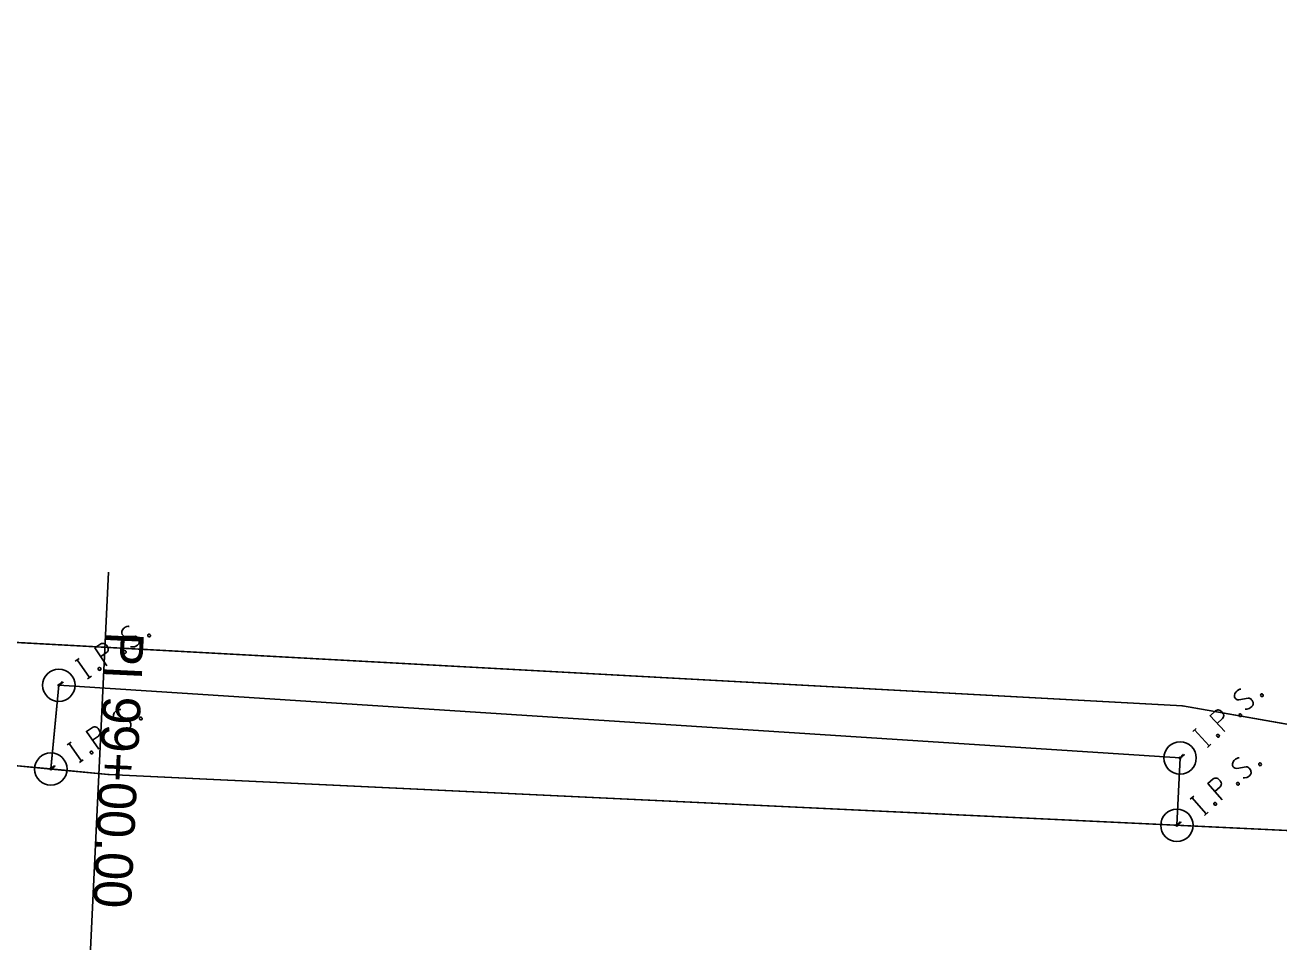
# Model space of a CAD drawing. Extents: x 2318731 to 2320621, y 732958 to 734198.
# Drawn here: x 2319231.8 to 2319324.8, y 733560.7 to 733628.7 of the extents above; entities that cross this region are included whole.
import ezdxf

# ---------------------------------------------------------------- set-up
doc = ezdxf.new("R2010")
doc.units = 0
for name, color, linetype in [('RW_P_Easement_Area', 7, 'Continuous'), ('RW_P_Esmt_SW', 7, 'Continuous'), ('RW_P_Esmt_TMP', 7, 'Continuous'), ('RW_P_Taking_Area', 7, 'Continuous'), ('RW_X_CL_100_Cardinal_Points', 7, 'Continuous'), ('RW_X_CL_500_Cardinal_Points', 7, 'Continuous'), ('SC_Scratch2', 7, 'Continuous'), ('SC_Scratch3', 7, 'Continuous'), ('SC_Scratch4', 7, 'Continuous'), ('SV_P_Control_Cells_Set', 7, 'Continuous'), ('SV_P_Mon_Cells_Set', 7, 'Continuous'), ('V-SURV-PARL-LINE', 7, 'Continuous')]:
    doc.layers.add(name, color=color, linetype=linetype)

msp = doc.modelspace()

# ---------------------------------------------------------------- linework, layer by layer
at = {"layer": 'RW_P_Easement_Area'}
for p, q in [((2319228.625, 733583.014), (2319317.642, 733578.163)), ((2319234.336, 733579.7), (2319233.745, 733573.486)), ((2319317.458, 733574.308), (2319234.336, 733579.7)), ((2319317.642, 733578.163), (2319387.147, 733565.99)), ((2319233.745, 733573.486), (2319227.772, 733574.054)), ((2319317.22, 733569.314), (2319317.458, 733574.308)), ((2319387.147, 733565.99), (2319317.22, 733569.314))]:
    msp.add_line(p, q, dxfattribs=at)
at = {"layer": 'RW_P_Esmt_SW'}
for p, q in [((2319233.745, 733573.486), (2319234.336, 733579.7)), ((2319233.745, 733573.486), (2319234.336, 733579.7)), ((2319234.336, 733579.7), (2319317.458, 733574.308)), ((2319234.336, 733579.7), (2319317.458, 733574.308)), ((2319317.458, 733574.308), (2319317.22, 733569.314)), ((2319317.458, 733574.308), (2319317.22, 733569.314))]:
    msp.add_line(p, q, dxfattribs=at)
at = {"layer": 'RW_P_Esmt_TMP'}
for p, q in [((2319228.625, 733583.016), (2319317.642, 733578.163)), ((2319317.642, 733578.163), (2319387.148, 733565.99))]:
    msp.add_line(p, q, dxfattribs=at)
at = {"layer": 'RW_P_Taking_Area'}
for p, q in [((2319233.745, 733573.486), (2319234.336, 733579.7)), ((2319234.336, 733579.7), (2319317.458, 733574.308)), ((2319317.458, 733574.308), (2319317.22, 733569.314)), ((2319238.014, 733573.079), (2319233.745, 733573.486)), ((2319317.22, 733569.314), (2319238.014, 733573.079))]:
    msp.add_line(p, q, dxfattribs=at)
at = {"layer": 'RW_X_CL_100_Cardinal_Points'}
msp.add_line((2319235.879, 733543.147), (2319238.016, 733588.096), dxfattribs=at)
at = {"layer": 'RW_X_CL_500_Cardinal_Points'}
msp.add_line((2319235.879, 733543.147), (2319238.016, 733588.096), dxfattribs=at)
at = {"layer": 'SC_Scratch2'}
msp.add_lwpolyline([(2319234.336, 733579.7), (2319317.451, 733574.309), (2319317.213, 733569.314), (2319238.014, 733573.079), (2319233.745, 733573.491)], close=True, dxfattribs=at)
at = {"layer": 'SC_Scratch3'}
msp.add_lwpolyline([(2319228.625, 733583.016), (2319227.772, 733574.054), (2319233.745, 733573.491), (2319234.336, 733579.7), (2319317.451, 733574.309), (2319317.213, 733569.314), (2319387.148, 733565.99), (2319317.634, 733578.164)], close=True, dxfattribs=at)
at = {"layer": 'SC_Scratch4'}
msp.add_lwpolyline([(2319238.014, 733573.079), (2319387.148, 733565.99), (2319438.367, 733857.203), (2319458.709, 733857.406), (2319402.048, 733535.248), (2319235.879, 733543.147), (2319201.733, 733546.397), (2319204.577, 733576.262)], close=True, dxfattribs=at)
at = {"layer": 'SV_P_Control_Cells_Set'}
for p, q in [((2319317.64, 733578.116), (2319317.645, 733578.21)), ((2319317.595, 733578.165), (2319317.69, 733578.161)), ((2319237.967, 733573.084), (2319238.061, 733573.075)), ((2319238.01, 733573.032), (2319238.018, 733573.126))]:
    msp.add_line(p, q, dxfattribs=at)
at = {"layer": 'SV_P_Mon_Cells_Set'}
for points in [[(2319239.559, 733584.062), (2319239.527, 733584.071), (2319239.485, 733584.073), (2319239.382, 733584.049), (2319239.267, 733584.002), (2319239.194, 733583.952), (2319239.167, 733583.934), (2319239.069, 733583.822), (2319239.011, 733583.692), (2319239.004, 733583.565), (2319239.042, 733583.469), (2319239.084, 733583.406), (2319239.159, 733583.335), (2319239.282, 733583.312), (2319239.996, 733583.338), (2319240.069, 733583.327), (2319240.116, 733583.298), (2319240.176, 733583.248), (2319240.219, 733583.185), (2319240.252, 733583.116), (2319240.271, 733583.068), (2319240.288, 733583.004), (2319240.298, 733582.95), (2319240.301, 733582.906), (2319240.295, 733582.856), (2319240.281, 733582.817), (2319240.259, 733582.771), (2319240.239, 733582.742), (2319240.164, 733582.676), (2319240.036, 733582.59), (2319239.939, 733582.555), (2319239.771, 733582.548), (2319239.656, 733582.561)], [(2319240.948, 733583.465), (2319240.993, 733583.496), (2319241.035, 733583.493), (2319241.09, 733583.47), (2319241.126, 733583.418), (2319241.127, 733583.358), (2319241.113, 733583.318), (2319241.068, 733583.287), (2319241.026, 733583.29), (2319240.971, 733583.313), (2319240.935, 733583.365), (2319240.934, 733583.426), (2319240.948, 733583.465)], [(2319237.899, 733581.145), (2319237.003, 733582.471), (2319237.441, 733582.767), (2319237.494, 733582.787), (2319237.572, 733582.81), (2319237.613, 733582.807), (2319237.655, 733582.805), (2319237.727, 733582.778), (2319237.789, 733582.744), (2319237.864, 733582.673), (2319237.949, 733582.547), (2319237.968, 733582.5), (2319237.992, 733582.425), (2319238.005, 733582.327), (2319237.989, 733582.271), (2319237.976, 733582.231), (2319237.945, 733582.18), (2319237.879, 733582.12), (2319237.44, 733581.824)], [(2319239.14, 733582.243), (2319239.185, 733582.273), (2319239.227, 733582.271), (2319239.282, 733582.248), (2319239.318, 733582.196), (2319239.319, 733582.135), (2319239.305, 733582.096), (2319239.26, 733582.065), (2319239.218, 733582.067), (2319239.162, 733582.091), (2319239.127, 733582.143), (2319239.126, 733582.203), (2319239.14, 733582.243)], [(2319235.56, 733581.495), (2319235.852, 733581.693)], [(2319236.602, 733580.268), (2319235.706, 733581.594)], [(2319237.277, 733580.983), (2319237.322, 733581.014), (2319237.364, 733581.012), (2319237.419, 733580.988), (2319237.455, 733580.936), (2319237.456, 733580.876), (2319237.442, 733580.836), (2319237.397, 733580.806), (2319237.355, 733580.808), (2319237.3, 733580.831), (2319237.264, 733580.883), (2319237.263, 733580.944), (2319237.277, 733580.983)], [(2319236.456, 733580.17), (2319236.748, 733580.367)], [(2319234.389, 733579.795), (2319234.402, 733579.807)], [(2319234.446, 733579.739), (2319234.395, 733579.801)], [(2319234.44, 733579.734), (2319234.453, 733579.745)], [(2319234.507, 733579.789), (2319234.456, 733579.851), (2319234.476, 733579.868), (2319234.479, 733579.869), (2319234.482, 733579.871), (2319234.485, 733579.871), (2319234.487, 733579.871), (2319234.49, 733579.87), (2319234.494, 733579.868), (2319234.498, 733579.865), (2319234.502, 733579.859), (2319234.504, 733579.857), (2319234.505, 733579.853), (2319234.506, 733579.849), (2319234.506, 733579.846), (2319234.505, 733579.844), (2319234.504, 733579.841), (2319234.501, 733579.838), (2319234.481, 733579.821)], [(2319234.477, 733579.778), (2319234.479, 733579.78), (2319234.481, 733579.78), (2319234.484, 733579.779), (2319234.486, 733579.777), (2319234.486, 733579.774), (2319234.485, 733579.772), (2319234.483, 733579.77), (2319234.481, 733579.77), (2319234.478, 733579.771), (2319234.476, 733579.773), (2319234.476, 733579.776), (2319234.477, 733579.778)], [(2319234.575, 733579.942), (2319234.574, 733579.943), (2319234.572, 733579.943), (2319234.567, 733579.941), (2319234.561, 733579.938), (2319234.558, 733579.935), (2319234.556, 733579.934), (2319234.552, 733579.928), (2319234.55, 733579.921), (2319234.55, 733579.915), (2319234.552, 733579.91), (2319234.555, 733579.907), (2319234.559, 733579.904), (2319234.565, 733579.904), (2319234.601, 733579.908), (2319234.604, 733579.908), (2319234.607, 733579.907), (2319234.61, 733579.905), (2319234.612, 733579.902), (2319234.614, 733579.899), (2319234.616, 733579.896), (2319234.617, 733579.893), (2319234.617, 733579.891), (2319234.618, 733579.888), (2319234.618, 733579.886), (2319234.617, 733579.884), (2319234.616, 733579.881), (2319234.615, 733579.88), (2319234.612, 733579.876), (2319234.606, 733579.871), (2319234.601, 733579.869), (2319234.593, 733579.868), (2319234.587, 733579.868)], [(2319234.563, 733579.85), (2319234.565, 733579.852), (2319234.567, 733579.852), (2319234.57, 733579.851), (2319234.572, 733579.848), (2319234.573, 733579.845), (2319234.572, 733579.843), (2319234.57, 733579.842), (2319234.568, 733579.841), (2319234.565, 733579.842), (2319234.563, 733579.845), (2319234.563, 733579.848), (2319234.563, 733579.85)], [(2319234.647, 733579.919), (2319234.649, 733579.921), (2319234.652, 733579.921), (2319234.654, 733579.92), (2319234.656, 733579.918), (2319234.657, 733579.915), (2319234.656, 733579.913), (2319234.654, 733579.911), (2319234.652, 733579.911), (2319234.649, 733579.912), (2319234.647, 733579.914), (2319234.647, 733579.917), (2319234.647, 733579.919)], [(2319321.971, 733579.401), (2319321.938, 733579.404), (2319321.896, 733579.401), (2319321.798, 733579.361), (2319321.691, 733579.298), (2319321.627, 733579.238), (2319321.602, 733579.215), (2319321.522, 733579.09), (2319321.485, 733578.953), (2319321.496, 733578.826), (2319321.548, 733578.737), (2319321.599, 733578.682), (2319321.684, 733578.622), (2319321.808, 733578.617), (2319322.51, 733578.75), (2319322.585, 733578.751), (2319322.635, 733578.728), (2319322.703, 733578.688), (2319322.754, 733578.632), (2319322.797, 733578.569), (2319322.823, 733578.525), (2319322.85, 733578.463), (2319322.868, 733578.411), (2319322.877, 733578.369), (2319322.878, 733578.318), (2319322.871, 733578.277), (2319322.856, 733578.229), (2319322.84, 733578.197), (2319322.775, 733578.121), (2319322.662, 733578.016), (2319322.572, 733577.968), (2319322.407, 733577.935), (2319322.291, 733577.931)], [(2319323.433, 733579.018), (2319323.473, 733579.055), (2319323.515, 733579.059), (2319323.573, 733579.044), (2319323.616, 733578.998), (2319323.626, 733578.939), (2319323.619, 733578.898), (2319323.578, 733578.86), (2319323.537, 733578.856), (2319323.478, 733578.871), (2319323.436, 733578.917), (2319323.426, 733578.977), (2319323.433, 733579.018)], [(2319238.931, 733577.891), (2319238.898, 733577.899), (2319238.857, 733577.901), (2319238.754, 733577.876), (2319238.639, 733577.828), (2319238.567, 733577.778), (2319238.54, 733577.76), (2319238.443, 733577.647), (2319238.386, 733577.516), (2319238.38, 733577.389), (2319238.419, 733577.294), (2319238.461, 733577.231), (2319238.537, 733577.161), (2319238.659, 733577.138), (2319239.373, 733577.171), (2319239.447, 733577.161), (2319239.494, 733577.132), (2319239.555, 733577.082), (2319239.598, 733577.02), (2319239.631, 733576.951), (2319239.651, 733576.903), (2319239.668, 733576.839), (2319239.679, 733576.785), (2319239.682, 733576.741), (2319239.676, 733576.691), (2319239.663, 733576.652), (2319239.641, 733576.606), (2319239.621, 733576.577), (2319239.547, 733576.51), (2319239.42, 733576.423), (2319239.324, 733576.387), (2319239.155, 733576.379), (2319239.04, 733576.391)], [(2319240.324, 733577.306), (2319240.369, 733577.337), (2319240.411, 733577.335), (2319240.467, 733577.312), (2319240.503, 733577.26), (2319240.504, 733577.2), (2319240.491, 733577.16), (2319240.446, 733577.129), (2319240.404, 733577.131), (2319240.348, 733577.154), (2319240.313, 733577.206), (2319240.311, 733577.266), (2319240.324, 733577.306)], [(2319320.765, 733576.269), (2319319.681, 733577.445), (2319320.07, 733577.804), (2319320.119, 733577.832), (2319320.193, 733577.866), (2319320.234, 733577.869), (2319320.276, 733577.873), (2319320.351, 733577.857), (2319320.418, 733577.833), (2319320.502, 733577.774), (2319320.605, 733577.663), (2319320.631, 733577.618), (2319320.666, 733577.547), (2319320.693, 733577.453), (2319320.686, 733577.395), (2319320.679, 733577.354), (2319320.656, 733577.298), (2319320.599, 733577.229), (2319320.21, 733576.871)], [(2319321.828, 733577.539), (2319321.868, 733577.576), (2319321.91, 733577.58), (2319321.968, 733577.566), (2319322.011, 733577.519), (2319322.021, 733577.46), (2319322.013, 733577.419), (2319321.973, 733577.381), (2319321.932, 733577.378), (2319321.873, 733577.392), (2319321.83, 733577.439), (2319321.82, 733577.498), (2319321.828, 733577.539)], [(2319237.295, 733574.96), (2319236.388, 733576.278), (2319236.824, 733576.578), (2319236.876, 733576.599), (2319236.954, 733576.622), (2319236.996, 733576.62), (2319237.037, 733576.618), (2319237.109, 733576.591), (2319237.172, 733576.558), (2319237.247, 733576.488), (2319237.333, 733576.363), (2319237.353, 733576.315), (2319237.377, 733576.24), (2319237.391, 733576.143), (2319237.376, 733576.087), (2319237.363, 733576.047), (2319237.332, 733575.995), (2319237.266, 733575.935), (2319236.831, 733575.635)], [(2319318.4, 733576.265), (2319318.659, 733576.504)], [(2319319.614, 733575.208), (2319318.53, 733576.385)], [(2319234.953, 733575.291), (2319235.244, 733575.491)], [(2319236.006, 733574.073), (2319235.098, 733575.391)], [(2319238.526, 733576.068), (2319238.572, 733576.099), (2319238.613, 733576.097), (2319238.669, 733576.075), (2319238.705, 733576.023), (2319238.706, 733575.962), (2319238.693, 733575.923), (2319238.648, 733575.892), (2319238.606, 733575.894), (2319238.551, 733575.916), (2319238.515, 733575.968), (2319238.513, 733576.029), (2319238.526, 733576.068)], [(2319320.174, 733576.015), (2319320.214, 733576.053), (2319320.256, 733576.057), (2319320.314, 733576.042), (2319320.357, 733575.995), (2319320.367, 733575.936), (2319320.36, 733575.895), (2319320.319, 733575.858), (2319320.278, 733575.854), (2319320.219, 733575.869), (2319320.177, 733575.915), (2319320.167, 733575.974), (2319320.174, 733576.015)], [(2319236.674, 733574.793), (2319236.719, 733574.824), (2319236.761, 733574.822), (2319236.817, 733574.799), (2319236.853, 733574.748), (2319236.854, 733574.687), (2319236.841, 733574.648), (2319236.796, 733574.617), (2319236.754, 733574.619), (2319236.698, 733574.641), (2319236.663, 733574.693), (2319236.661, 733574.753), (2319236.674, 733574.793)], [(2319317.624, 733574.404), (2319317.571, 733574.464), (2319317.59, 733574.481), (2319317.593, 733574.483), (2319317.596, 733574.485), (2319317.598, 733574.485), (2319317.6, 733574.485), (2319317.604, 733574.484), (2319317.607, 733574.483), (2319317.612, 733574.48), (2319317.617, 733574.474), (2319317.618, 733574.472), (2319317.62, 733574.468), (2319317.621, 733574.464), (2319317.621, 733574.461), (2319317.62, 733574.459), (2319317.619, 733574.456), (2319317.616, 733574.453), (2319317.597, 733574.435)], [(2319317.686, 733574.561), (2319317.684, 733574.561), (2319317.682, 733574.561), (2319317.677, 733574.559), (2319317.672, 733574.556), (2319317.668, 733574.553), (2319317.667, 733574.552), (2319317.663, 733574.545), (2319317.661, 733574.538), (2319317.662, 733574.532), (2319317.664, 733574.528), (2319317.667, 733574.525), (2319317.671, 733574.522), (2319317.677, 733574.522), (2319317.712, 733574.528), (2319317.716, 733574.528), (2319317.719, 733574.527), (2319317.722, 733574.525), (2319317.725, 733574.522), (2319317.727, 733574.519), (2319317.728, 733574.517), (2319317.729, 733574.514), (2319317.73, 733574.511), (2319317.731, 733574.509), (2319317.731, 733574.506), (2319317.73, 733574.504), (2319317.73, 733574.502), (2319317.729, 733574.5), (2319317.725, 733574.496), (2319317.72, 733574.491), (2319317.715, 733574.489), (2319317.707, 733574.487), (2319317.701, 733574.487)], [(2319317.678, 733574.468), (2319317.68, 733574.47), (2319317.682, 733574.47), (2319317.685, 733574.469), (2319317.687, 733574.467), (2319317.688, 733574.464), (2319317.687, 733574.462), (2319317.685, 733574.46), (2319317.683, 733574.46), (2319317.68, 733574.46), (2319317.678, 733574.463), (2319317.678, 733574.466), (2319317.678, 733574.468)], [(2319317.759, 733574.541), (2319317.761, 733574.543), (2319317.763, 733574.543), (2319317.766, 733574.542), (2319317.768, 733574.54), (2319317.768, 733574.537), (2319317.768, 733574.535), (2319317.766, 733574.533), (2319317.764, 733574.533), (2319317.761, 733574.534), (2319317.759, 733574.536), (2319317.758, 733574.539), (2319317.759, 733574.541)], [(2319319.484, 733575.088), (2319319.744, 733575.327)], [(2319233.797, 733573.581), (2319233.811, 733573.592)], [(2319233.855, 733573.525), (2319233.804, 733573.586)], [(2319233.915, 733573.574), (2319233.864, 733573.636), (2319233.884, 733573.653), (2319233.887, 733573.654), (2319233.891, 733573.656), (2319233.893, 733573.656), (2319233.895, 733573.656), (2319233.899, 733573.655), (2319233.902, 733573.654), (2319233.906, 733573.65), (2319233.911, 733573.645), (2319233.912, 733573.642), (2319233.914, 733573.639), (2319233.915, 733573.634), (2319233.914, 733573.631), (2319233.914, 733573.629), (2319233.912, 733573.626), (2319233.909, 733573.623), (2319233.889, 733573.606)], [(2319233.885, 733573.563), (2319233.887, 733573.565), (2319233.889, 733573.565), (2319233.892, 733573.564), (2319233.894, 733573.562), (2319233.894, 733573.559), (2319233.894, 733573.557), (2319233.892, 733573.555), (2319233.89, 733573.555), (2319233.887, 733573.556), (2319233.885, 733573.558), (2319233.884, 733573.561), (2319233.885, 733573.563)], [(2319233.984, 733573.728), (2319233.982, 733573.728), (2319233.98, 733573.728), (2319233.975, 733573.726), (2319233.969, 733573.723), (2319233.966, 733573.72), (2319233.965, 733573.719), (2319233.96, 733573.713), (2319233.958, 733573.707), (2319233.958, 733573.7), (2319233.961, 733573.696), (2319233.963, 733573.693), (2319233.967, 733573.69), (2319233.973, 733573.689), (2319234.009, 733573.694), (2319234.013, 733573.694), (2319234.015, 733573.692), (2319234.018, 733573.69), (2319234.021, 733573.687), (2319234.023, 733573.684), (2319234.024, 733573.682), (2319234.025, 733573.678), (2319234.026, 733573.676), (2319234.026, 733573.674), (2319234.026, 733573.671), (2319234.026, 733573.669), (2319234.025, 733573.667), (2319234.024, 733573.665), (2319234.02, 733573.662), (2319234.014, 733573.657), (2319234.01, 733573.654), (2319234.002, 733573.653), (2319233.996, 733573.653)], [(2319233.972, 733573.635), (2319233.974, 733573.637), (2319233.976, 733573.637), (2319233.979, 733573.636), (2319233.981, 733573.634), (2319233.981, 733573.631), (2319233.98, 733573.629), (2319233.978, 733573.627), (2319233.976, 733573.627), (2319233.973, 733573.628), (2319233.971, 733573.63), (2319233.971, 733573.633), (2319233.972, 733573.635)], [(2319234.056, 733573.705), (2319234.058, 733573.706), (2319234.06, 733573.706), (2319234.063, 733573.706), (2319234.065, 733573.703), (2319234.065, 733573.7), (2319234.065, 733573.698), (2319234.062, 733573.696), (2319234.06, 733573.696), (2319234.058, 733573.697), (2319234.056, 733573.7), (2319234.055, 733573.703), (2319234.056, 733573.705)], [(2319235.86, 733573.973), (2319236.151, 733574.173)], [(2319317.506, 733574.405), (2319317.519, 733574.417)], [(2319317.566, 733574.352), (2319317.513, 733574.411)], [(2319317.56, 733574.346), (2319317.573, 733574.358)], [(2319317.595, 733574.392), (2319317.597, 733574.394), (2319317.599, 733574.394), (2319317.602, 733574.393), (2319317.604, 733574.391), (2319317.604, 733574.388), (2319317.604, 733574.386), (2319317.602, 733574.384), (2319317.6, 733574.384), (2319317.597, 733574.385), (2319317.595, 733574.387), (2319317.594, 733574.39), (2319317.595, 733574.392)], [(2319321.837, 733574.312), (2319321.804, 733574.317), (2319321.763, 733574.314), (2319321.663, 733574.276), (2319321.556, 733574.215), (2319321.49, 733574.157), (2319321.465, 733574.135), (2319321.383, 733574.011), (2319321.342, 733573.874), (2319321.351, 733573.748), (2319321.401, 733573.658), (2319321.451, 733573.601), (2319321.534, 733573.54), (2319321.659, 733573.532), (2319322.363, 733573.651), (2319322.438, 733573.649), (2319322.488, 733573.626), (2319322.554, 733573.584), (2319322.604, 733573.528), (2319322.646, 733573.464), (2319322.671, 733573.419), (2319322.696, 733573.357), (2319322.713, 733573.304), (2319322.722, 733573.262), (2319322.722, 733573.211), (2319322.714, 733573.17), (2319322.698, 733573.122), (2319322.681, 733573.091), (2319322.615, 733573.016), (2319322.499, 733572.914), (2319322.409, 733572.867), (2319322.243, 733572.838), (2319322.126, 733572.836)], [(2319323.291, 733573.899), (2319323.332, 733573.936), (2319323.374, 733573.939), (2319323.432, 733573.923), (2319323.474, 733573.875), (2319323.482, 733573.816), (2319323.474, 733573.775), (2319323.433, 733573.739), (2319323.391, 733573.735), (2319323.333, 733573.751), (2319323.292, 733573.799), (2319323.283, 733573.858), (2319323.291, 733573.899)], [(2319233.848, 733573.519), (2319233.862, 733573.53)], [(2319320.567, 733571.206), (2319319.507, 733572.405), (2319319.904, 733572.755), (2319319.953, 733572.782), (2319320.028, 733572.814), (2319320.069, 733572.817), (2319320.111, 733572.82), (2319320.185, 733572.802), (2319320.252, 733572.777), (2319320.335, 733572.716), (2319320.435, 733572.603), (2319320.46, 733572.558), (2319320.494, 733572.487), (2319320.519, 733572.391), (2319320.511, 733572.334), (2319320.503, 733572.293), (2319320.479, 733572.238), (2319320.421, 733572.17), (2319320.024, 733571.819)], [(2319321.656, 733572.454), (2319321.697, 733572.49), (2319321.738, 733572.493), (2319321.796, 733572.478), (2319321.838, 733572.43), (2319321.847, 733572.371), (2319321.839, 733572.33), (2319321.797, 733572.293), (2319321.756, 733572.29), (2319321.698, 733572.306), (2319321.656, 733572.354), (2319321.647, 733572.413), (2319321.656, 733572.454)], [(2319318.202, 733571.252), (2319318.466, 733571.485)], [(2319319.394, 733570.169), (2319318.334, 733571.368)], [(2319319.97, 733570.965), (2319320.012, 733571.001), (2319320.053, 733571.004), (2319320.111, 733570.989), (2319320.153, 733570.941), (2319320.162, 733570.882), (2319320.154, 733570.841), (2319320.112, 733570.804), (2319320.071, 733570.801), (2319320.013, 733570.817), (2319319.971, 733570.865), (2319319.962, 733570.924), (2319319.97, 733570.965)], [(2319319.261, 733570.053), (2319319.526, 733570.286)], [(2319317.268, 733569.412), (2319317.281, 733569.423)], [(2319317.328, 733569.358), (2319317.274, 733569.417)], [(2319317.321, 733569.352), (2319317.334, 733569.364)], [(2319317.386, 733569.411), (2319317.332, 733569.47), (2319317.352, 733569.488), (2319317.354, 733569.489), (2319317.358, 733569.491), (2319317.36, 733569.491), (2319317.362, 733569.491), (2319317.366, 733569.49), (2319317.369, 733569.489), (2319317.373, 733569.486), (2319317.378, 733569.481), (2319317.38, 733569.478), (2319317.381, 733569.475), (2319317.383, 733569.47), (2319317.382, 733569.467), (2319317.382, 733569.465), (2319317.381, 733569.462), (2319317.378, 733569.459), (2319317.358, 733569.441)], [(2319317.356, 733569.398), (2319317.358, 733569.4), (2319317.36, 733569.4), (2319317.363, 733569.4), (2319317.365, 733569.397), (2319317.366, 733569.394), (2319317.365, 733569.392), (2319317.363, 733569.391), (2319317.361, 733569.39), (2319317.358, 733569.391), (2319317.356, 733569.393), (2319317.356, 733569.396), (2319317.356, 733569.398)], [(2319317.447, 733569.567), (2319317.446, 733569.567), (2319317.443, 733569.567), (2319317.439, 733569.565), (2319317.433, 733569.562), (2319317.43, 733569.559), (2319317.429, 733569.558), (2319317.425, 733569.552), (2319317.423, 733569.545), (2319317.423, 733569.539), (2319317.426, 733569.534), (2319317.428, 733569.531), (2319317.433, 733569.528), (2319317.439, 733569.528), (2319317.474, 733569.534), (2319317.478, 733569.534), (2319317.48, 733569.533), (2319317.484, 733569.531), (2319317.486, 733569.528), (2319317.488, 733569.525), (2319317.49, 733569.523), (2319317.491, 733569.52), (2319317.492, 733569.517), (2319317.492, 733569.515), (2319317.492, 733569.513), (2319317.492, 733569.511), (2319317.491, 733569.508), (2319317.49, 733569.507), (2319317.487, 733569.503), (2319317.481, 733569.498), (2319317.477, 733569.495), (2319317.468, 733569.494), (2319317.463, 733569.494)], [(2319317.439, 733569.474), (2319317.441, 733569.476), (2319317.444, 733569.476), (2319317.446, 733569.475), (2319317.449, 733569.473), (2319317.449, 733569.47), (2319317.449, 733569.468), (2319317.447, 733569.466), (2319317.445, 733569.466), (2319317.442, 733569.467), (2319317.44, 733569.469), (2319317.439, 733569.472), (2319317.439, 733569.474)], [(2319317.52, 733569.547), (2319317.522, 733569.549), (2319317.524, 733569.549), (2319317.527, 733569.549), (2319317.529, 733569.546), (2319317.53, 733569.543), (2319317.529, 733569.541), (2319317.527, 733569.54), (2319317.525, 733569.539), (2319317.522, 733569.54), (2319317.52, 733569.542), (2319317.52, 733569.545), (2319317.52, 733569.547)]]:
    msp.add_lwpolyline(points, dxfattribs=at)
for centre, radius in [((2319234.336, 733579.7), 1.2), ((2319234.336, 733579.7), 0.06), ((2319317.458, 733574.308), 1.2), ((2319233.745, 733573.486), 1.2), ((2319233.745, 733573.486), 0.06), ((2319317.458, 733574.308), 0.06), ((2319317.22, 733569.314), 1.2), ((2319317.22, 733569.314), 0.06)]:
    msp.add_circle(centre, radius, dxfattribs=at)
at = {"layer": 'V-SURV-PARL-LINE'}
for p, q in [((2318854.927, 733609.549), (2319237.974, 733573.083)), ((2319238.014, 733573.079), (2319387.148, 733565.99))]:
    msp.add_line(p, q, dxfattribs=at)

# ---------------------------------------------------------------- texts
at = {"layer": 'RW_X_CL_100_Cardinal_Points'}
for s, p in [('PI', (2319237.855, 733583.717)), ('99+00.00', (2319237.627, 733578.94))]:
    msp.add_text(s, height=2.8, rotation=267.27847, dxfattribs=at).set_placement(p)
at = {"layer": 'RW_X_CL_500_Cardinal_Points'}
for s, p in [('PI', (2319237.855, 733583.717)), ('99+00.00', (2319237.627, 733578.94))]:
    msp.add_text(s, height=2.8, rotation=267.27847, dxfattribs=at).set_placement(p)

doc.saveas('drawing.dxf')
